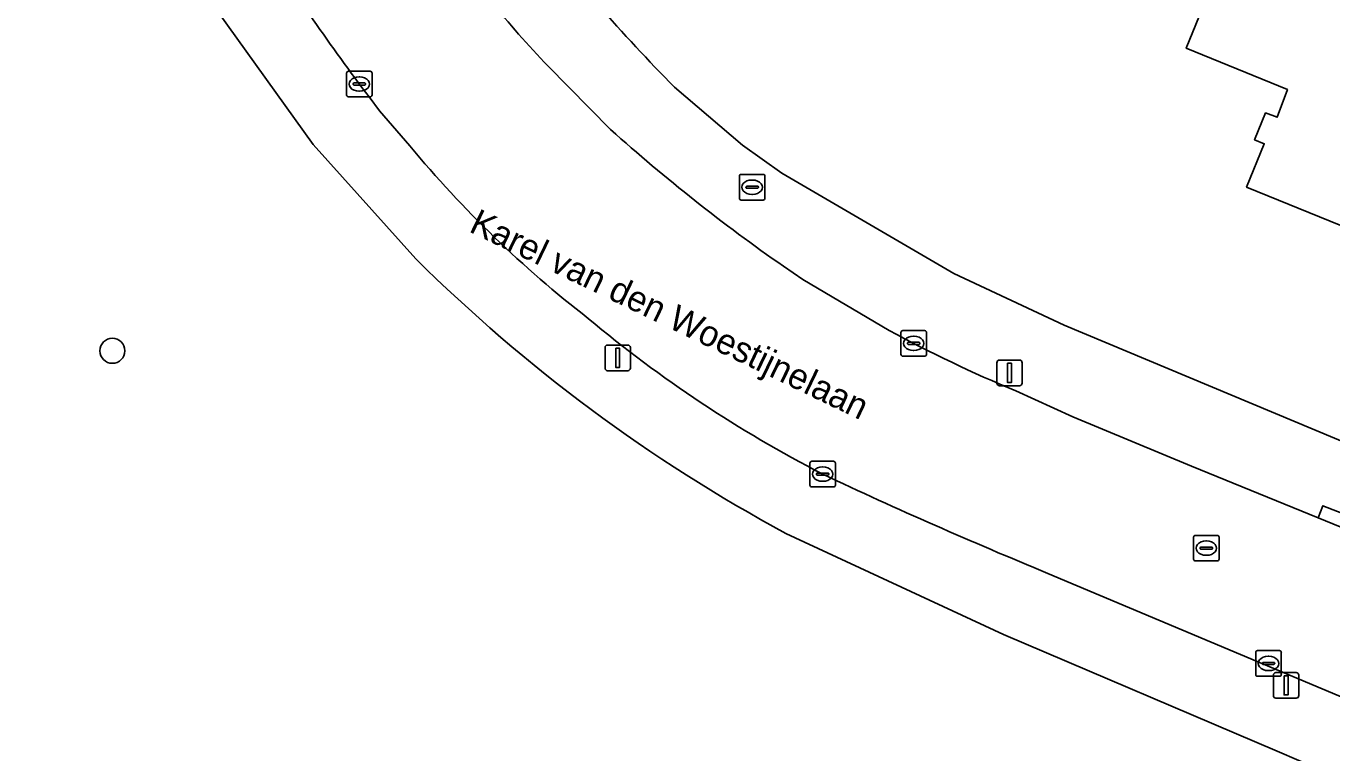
# Model space of a CAD drawing. Extents: x 161139 to 161601, y 381708 to 382245.
# Drawn here: x 161257.4 to 161308.4, y 381871.1 to 381899.5 of the extents above; entities that cross this region are included whole.
import ezdxf

# ---------------------------------------------------------------- set-up
doc = ezdxf.new("R2010")
doc.units = 0
for name, color, linetype in [('IMGEO_Boom', 7, 'Continuous'), ('IMGEO_Brandkraan', 7, 'Continuous'), ('IMGEO_Erf', 7, 'Continuous'), ('IMGEO_Groenvoorziening', 7, 'Continuous'), ('IMGEO_Kolk', 7, 'Continuous'), ('IMGEO_Lichtmast', 7, 'Continuous'), ('IMGEO_Openbare_ruimte_label', 7, 'Continuous'), ('IMGEO_Pand', 7, 'Continuous'), ('IMGEO_Rijbaan_lokaal_open', 7, 'Continuous'), ('IMGEO_Rioolput', 7, 'Continuous'), ('IMGEO_Voetpad_open', 7, 'Continuous')]:
    doc.layers.add(name, color=color, linetype=linetype)

msp = doc.modelspace()

# ---------------------------------------------------------------- linework, layer by layer
at = {"layer": 'IMGEO_Boom'}
msp.add_circle((161260.788, 381886.858), 0.489, dxfattribs=at)
at = {"layer": 'IMGEO_Brandkraan'}
for p, q in [((161285.289, 381892.824), (161285.289, 381893.676)), ((161285.364, 381893.75), (161286.216, 381893.75)), ((161285.777, 381893.53), (161285.802, 381893.53)), ((161286.29, 381893.676), (161286.29, 381892.824)), ((161285.548, 381893.244), (161285.548, 381893.256)), ((161285.986, 381893.207), (161285.588, 381893.207)), ((161285.591, 381893.293), (161285.989, 381893.293)), ((161286.032, 381893.256), (161286.032, 381893.244)), ((161286.216, 381892.75), (161285.364, 381892.75)), ((161285.8, 381892.97), (161285.775, 381892.97))]:
    msp.add_line(p, q, dxfattribs=at)
for points in [[(161285.289, 381892.824), (161285.289, 381893.676)], [(161285.364, 381893.75), (161286.216, 381893.75)], [(161286.29, 381893.676), (161286.29, 381892.824)], [(161286.216, 381892.75), (161285.364, 381892.75)]]:
    msp.add_lwpolyline(points, dxfattribs=at)
for centre, radius, start, end in [((161285.366, 381893.674), 0.0765, 91.552, 178.448), ((161285.366, 381893.674), 0.0765, 91.552, 178.448), ((161286.214, 381893.674), 0.0765, 1.552, 88.448), ((161286.214, 381893.674), 0.0765, 1.552, 88.448), ((161285.588, 381893.253), 0.0403, 85.8775, 175.7526), ((161285.585, 381893.243), 0.0366, 178.938, 274.7102), ((161285.989, 381893.25), 0.043, 264.8664, 352.4533), ((161285.993, 381893.255), 0.0386, 1.7309, 96.639), ((161285.366, 381892.826), 0.0765, 181.552, 268.448), ((161285.366, 381892.826), 0.0765, 181.552, 268.448), ((161286.214, 381892.826), 0.0765, 271.552, 358.448), ((161286.214, 381892.826), 0.0765, 271.552, 358.448)]:
    msp.add_arc(centre, radius, start, end, dxfattribs=at)
for centre, major_axis, ratio, start_param, end_param in [((161285.776, 381893.25), (-0.387, 0.002), 0.722429, 4.712389, 7.853982), ((161285.801, 381893.25), (-0.39, 0.002), 0.717154, 1.570796, 4.712389)]:
    msp.add_ellipse(centre, major_axis=major_axis, ratio=ratio, start_param=start_param, end_param=end_param, dxfattribs=at)
at = {"layer": 'IMGEO_Erf'}
msp.add_lwpolyline([(161316.193, 381910.265), (161323.278, 381907.381), (161321.194, 381902.259), (161317.489, 381903.766), (161313.947, 381895.06), (161312.062, 381890.428), (161305.111, 381893.257), (161305.8, 381894.95), (161305.424, 381895.103), (161305.852, 381896.154), (161306.302, 381895.986), (161306.706, 381897.067), (161302.753, 381898.676), (161306.145, 381907.012), (161310.258, 381905.339), (161309.82, 381904.264), (161313.34, 381902.832), (161314.245, 381905.055), (161314.097, 381905.115)], close=True, dxfattribs=at)
msp.add_lwpolyline([(161282.757, 381897.162), (161285.416, 381894.897), (161286.952, 381893.797), (161293.664, 381889.876), (161297.982, 381887.859), (161317.522, 381879.697)], dxfattribs=at)
msp.add_arc((161325.918, 381940.222), 60.967, 216.71398, 224.93243, dxfattribs=at)
at = {"layer": 'IMGEO_Groenvoorziening'}
for points in [[(161272.651, 381890.451), (161268.63, 381894.919), (161264.924, 381900.093), (161261.387, 381906.491)], [(161307.156, 381870.851), (161306.308, 381871.219), (161295.616, 381875.775), (161287.109, 381879.723)]]:
    msp.add_lwpolyline(points, dxfattribs=at)
msp.add_arc((161316.981, 381935.088), 62.91, 225.19754, 241.65079, dxfattribs=at)
at = {"layer": 'IMGEO_Kolk'}
for p, q in [((161269.938, 381896.854), (161269.938, 381897.706)), ((161270.013, 381897.78), (161270.865, 381897.78)), ((161270.939, 381897.706), (161270.939, 381896.854)), ((161270.197, 381897.274), (161270.197, 381897.286)), ((161270.635, 381897.237), (161270.237, 381897.237)), ((161270.24, 381897.323), (161270.638, 381897.323)), ((161270.426, 381897.56), (161270.451, 381897.56)), ((161270.681, 381897.286), (161270.681, 381897.274)), ((161270.865, 381896.78), (161270.013, 381896.78)), ((161270.449, 381897), (161270.424, 381897)), ((161291.601, 381886.722), (161291.601, 381887.574)), ((161291.676, 381887.648), (161292.528, 381887.648)), ((161292.089, 381887.428), (161292.114, 381887.428)), ((161292.602, 381887.574), (161292.602, 381886.722)), ((161291.86, 381887.142), (161291.86, 381887.154)), ((161292.298, 381887.105), (161291.9, 381887.105)), ((161291.903, 381887.191), (161292.301, 381887.191)), ((161292.344, 381887.154), (161292.344, 381887.142)), ((161292.528, 381886.648), (161291.676, 381886.648)), ((161292.112, 381886.868), (161292.087, 381886.868)), ((161288.043, 381881.614), (161288.043, 381882.466)), ((161288.118, 381882.54), (161288.97, 381882.54)), ((161288.531, 381882.32), (161288.556, 381882.32)), ((161289.044, 381882.466), (161289.044, 381881.614)), ((161288.302, 381882.034), (161288.302, 381882.046)), ((161288.74, 381881.997), (161288.342, 381881.997)), ((161288.345, 381882.083), (161288.743, 381882.083)), ((161288.786, 381882.046), (161288.786, 381882.034)), ((161288.97, 381881.54), (161288.118, 381881.54)), ((161288.554, 381881.76), (161288.529, 381881.76)), ((161305.541, 381875.143), (161306.393, 381875.143)), ((161305.466, 381874.217), (161305.466, 381875.069)), ((161305.725, 381874.637), (161305.725, 381874.649)), ((161305.768, 381874.686), (161306.166, 381874.686)), ((161305.954, 381874.923), (161305.979, 381874.923)), ((161306.209, 381874.649), (161306.209, 381874.637)), ((161306.467, 381875.069), (161306.467, 381874.217)), ((161306.393, 381874.143), (161305.541, 381874.143)), ((161306.163, 381874.6), (161305.765, 381874.6)), ((161305.977, 381874.363), (161305.952, 381874.363))]:
    msp.add_line(p, q, dxfattribs=at)
for points in [[(161269.938, 381896.854), (161269.938, 381897.706)], [(161270.013, 381897.78), (161270.865, 381897.78)], [(161270.939, 381897.706), (161270.939, 381896.854)], [(161270.865, 381896.78), (161270.013, 381896.78)], [(161291.601, 381886.722), (161291.601, 381887.574)], [(161291.676, 381887.648), (161292.528, 381887.648)], [(161292.602, 381887.574), (161292.602, 381886.722)], [(161292.528, 381886.648), (161291.676, 381886.648)], [(161288.043, 381881.614), (161288.043, 381882.466)], [(161288.118, 381882.54), (161288.97, 381882.54)], [(161289.044, 381882.466), (161289.044, 381881.614)], [(161288.97, 381881.54), (161288.118, 381881.54)], [(161305.541, 381875.143), (161306.393, 381875.143)], [(161305.466, 381874.217), (161305.466, 381875.069)], [(161306.467, 381875.069), (161306.467, 381874.217)], [(161306.393, 381874.143), (161305.541, 381874.143)]]:
    msp.add_lwpolyline(points, dxfattribs=at)
for centre, radius, start, end in [((161270.015, 381897.704), 0.0765, 91.552, 178.448), ((161270.015, 381897.704), 0.0765, 91.552, 178.448), ((161270.863, 381897.704), 0.0765, 1.552, 88.448), ((161270.863, 381897.704), 0.0765, 1.552, 88.448), ((161270.237, 381897.283), 0.0403, 85.8775, 175.7526), ((161270.234, 381897.273), 0.0366, 178.938, 274.7102), ((161270.638, 381897.28), 0.043, 264.8664, 352.4533), ((161270.642, 381897.285), 0.0386, 1.7309, 96.639), ((161270.015, 381896.856), 0.0765, 181.552, 268.448), ((161270.015, 381896.856), 0.0765, 181.552, 268.448), ((161270.863, 381896.856), 0.0765, 271.552, 358.448), ((161270.863, 381896.856), 0.0765, 271.552, 358.448), ((161291.678, 381887.572), 0.0765, 91.552, 178.448), ((161291.678, 381887.572), 0.0765, 91.552, 178.448), ((161292.526, 381887.572), 0.0765, 1.552, 88.448), ((161292.526, 381887.572), 0.0765, 1.552, 88.448), ((161291.9, 381887.151), 0.0403, 85.8775, 175.7526), ((161291.897, 381887.141), 0.0366, 178.938, 274.7102), ((161292.301, 381887.148), 0.043, 264.8664, 352.4533), ((161292.305, 381887.153), 0.0386, 1.7309, 96.639), ((161291.678, 381886.724), 0.0765, 181.552, 268.448), ((161291.678, 381886.724), 0.0765, 181.552, 268.448), ((161292.526, 381886.724), 0.0765, 271.552, 358.448), ((161292.526, 381886.724), 0.0765, 271.552, 358.448), ((161288.12, 381882.464), 0.0765, 91.552, 178.448), ((161288.12, 381882.464), 0.0765, 91.552, 178.448), ((161288.968, 381882.464), 0.0765, 1.552, 88.448), ((161288.968, 381882.464), 0.0765, 1.552, 88.448), ((161288.342, 381882.043), 0.0403, 85.8775, 175.7526), ((161288.339, 381882.033), 0.0366, 178.938, 274.7102), ((161288.743, 381882.04), 0.043, 264.8664, 352.4533), ((161288.747, 381882.045), 0.0386, 1.7309, 96.639), ((161288.12, 381881.616), 0.0765, 181.552, 268.448), ((161288.12, 381881.616), 0.0765, 181.552, 268.448), ((161288.968, 381881.616), 0.0765, 271.552, 358.448), ((161288.968, 381881.616), 0.0765, 271.552, 358.448), ((161305.543, 381875.067), 0.0765, 91.552, 178.448), ((161305.543, 381875.067), 0.0765, 91.552, 178.448), ((161306.391, 381875.067), 0.0765, 1.552, 88.448), ((161306.391, 381875.067), 0.0765, 1.552, 88.448), ((161305.765, 381874.646), 0.0403, 85.8775, 175.7526), ((161305.762, 381874.636), 0.0366, 178.938, 274.7102), ((161306.166, 381874.643), 0.043, 264.8664, 352.4533), ((161306.17, 381874.648), 0.0386, 1.7309, 96.639), ((161305.543, 381874.219), 0.0765, 181.552, 268.448), ((161305.543, 381874.219), 0.0765, 181.552, 268.448), ((161306.391, 381874.219), 0.0765, 271.552, 358.448), ((161306.391, 381874.219), 0.0765, 271.552, 358.448)]:
    msp.add_arc(centre, radius, start, end, dxfattribs=at)
for centre, major_axis, ratio, start_param, end_param in [((161270.425, 381897.28), (-0.387, 0.002), 0.722429, 4.712389, 7.853982), ((161270.45, 381897.28), (-0.39, 0.002), 0.717154, 1.570796, 4.712389), ((161292.088, 381887.148), (-0.387, 0.002), 0.722429, 4.712389, 7.853982), ((161292.113, 381887.148), (-0.39, 0.002), 0.717154, 1.570796, 4.712389), ((161288.53, 381882.04), (-0.387, 0.002), 0.722429, 4.712389, 7.853982), ((161288.555, 381882.04), (-0.39, 0.002), 0.717154, 1.570796, 4.712389), ((161305.953, 381874.643), (-0.387, 0.002), 0.722429, 4.712389, 7.853982), ((161305.978, 381874.643), (-0.39, 0.002), 0.717154, 1.570796, 4.712389)]:
    msp.add_ellipse(centre, major_axis=major_axis, ratio=ratio, start_param=start_param, end_param=end_param, dxfattribs=at)
at = {"layer": 'IMGEO_Lichtmast'}
for p, q in [((161280.041, 381886.182), (161280.041, 381886.982)), ((161280.041, 381886.982), (161280.041, 381886.182)), ((161280.141, 381887.082), (161280.931, 381887.082)), ((161280.931, 381887.082), (161280.141, 381887.082)), ((161281.031, 381886.982), (161281.031, 381886.182)), ((161281.031, 381886.182), (161281.031, 381886.982)), ((161295.349, 381885.594), (161295.349, 381886.394)), ((161295.349, 381886.394), (161295.349, 381885.594)), ((161295.449, 381886.494), (161296.239, 381886.494)), ((161296.239, 381886.494), (161295.449, 381886.494)), ((161296.339, 381886.394), (161296.339, 381885.594)), ((161296.339, 381885.594), (161296.339, 381886.394)), ((161280.931, 381886.082), (161280.141, 381886.082)), ((161280.141, 381886.082), (161280.931, 381886.082)), ((161296.239, 381885.494), (161295.449, 381885.494)), ((161295.449, 381885.494), (161296.239, 381885.494)), ((161306.158, 381873.386), (161306.158, 381874.186)), ((161306.158, 381874.186), (161306.158, 381873.386)), ((161306.258, 381874.286), (161307.048, 381874.286)), ((161307.048, 381874.286), (161306.258, 381874.286)), ((161307.148, 381874.186), (161307.148, 381873.386)), ((161307.148, 381873.386), (161307.148, 381874.186)), ((161307.048, 381873.286), (161306.258, 381873.286)), ((161306.258, 381873.286), (161307.048, 381873.286))]:
    msp.add_line(p, q, dxfattribs=at)
for points in [[(161280.461, 381886.957), (161280.611, 381886.957), (161280.611, 381886.207), (161280.461, 381886.207), (161280.461, 381886.957)], [(161295.769, 381886.369), (161295.919, 381886.369), (161295.919, 381885.619), (161295.769, 381885.619), (161295.769, 381886.369)], [(161306.578, 381874.161), (161306.728, 381874.161), (161306.728, 381873.411), (161306.578, 381873.411), (161306.578, 381874.161)]]:
    msp.add_lwpolyline(points, dxfattribs=at)
for centre, start, end in [((161280.141, 381886.982), 90, 180), ((161280.141, 381886.982), 90, 180), ((161280.931, 381886.982), 0, 90), ((161280.931, 381886.982), 360, 90), ((161295.449, 381886.394), 90, 180), ((161295.449, 381886.394), 90, 180), ((161296.239, 381886.394), 0, 90), ((161296.239, 381886.394), 360, 90), ((161280.141, 381886.182), 180, 270), ((161280.141, 381886.182), 180, 270), ((161280.931, 381886.182), 270, 0), ((161280.931, 381886.182), 270, 0), ((161295.449, 381885.594), 180, 270), ((161295.449, 381885.594), 180, 270), ((161296.239, 381885.594), 270, 0), ((161296.239, 381885.594), 270, 0), ((161306.258, 381874.186), 90, 180), ((161306.258, 381874.186), 90, 180), ((161307.048, 381874.186), 0, 90), ((161307.048, 381874.186), 360, 90), ((161306.258, 381873.386), 180, 270), ((161306.258, 381873.386), 180, 270), ((161307.048, 381873.386), 270, 0), ((161307.048, 381873.386), 270, 0)]:
    msp.add_arc(centre, 0.1, start, end, dxfattribs=at)
at = {"layer": 'IMGEO_Pand'}
msp.add_lwpolyline([(161312.062, 381890.428), (161313.947, 381895.06), (161317.489, 381903.766), (161321.194, 381902.259), (161323.278, 381907.381), (161316.193, 381910.265), (161314.097, 381905.115), (161314.245, 381905.055), (161313.34, 381902.832), (161309.82, 381904.264), (161310.258, 381905.339), (161306.145, 381907.012), (161302.753, 381898.676), (161306.706, 381897.067), (161306.302, 381895.986), (161305.852, 381896.154), (161305.424, 381895.103), (161305.8, 381894.95), (161305.111, 381893.257)], close=True, dxfattribs=at)
at = {"layer": 'IMGEO_Rijbaan_lokaal_open'}
for points in [[(161280.259, 381895.503), (161277.808, 381897.987)], [(161270.816, 381896.775), (161271.228, 381896.235), (161272.414, 381894.865)], [(161291.143, 381887.655), (161287.77, 381889.643), (161287.39, 381889.901), (161287.011, 381890.162)], [(161321.429, 381875.549), (161318.426, 381876.273), (161316.431, 381876.868), (161312.405, 381878.498), (161307.913, 381880.338), (161302.959, 381882.345), (161298.323, 381884.279), (161296.095, 381885.289)], [(161297.345, 381878.162), (161313.303, 381871.448)]]:
    msp.add_lwpolyline(points, dxfattribs=at)
for centre, radius, start, end in [((161357.146, 381961.507), 107.903, 212.90543, 216.8632), ((161305.516, 381924.595), 38.415, 218.7964, 223.8402), ((161326.411, 381946.909), 69.084, 228.08278, 235.22747), ((161306.253, 381922.87), 43.924, 219.6115, 232.2855), ((161311.453, 381926.489), 50.005, 230.1076, 242.7376), ((161316.865, 381935.126), 53.992, 241.5489, 247.3754), ((161368.588, 382051.732), 187.622, 244.748, 247.68406)]:
    msp.add_arc(centre, radius, start, end, dxfattribs=at)
at = {"layer": 'IMGEO_Rioolput'}
for p, q in [((161303.035, 381878.722), (161303.035, 381879.574)), ((161303.11, 381879.648), (161303.962, 381879.648)), ((161303.523, 381879.428), (161303.548, 381879.428)), ((161304.036, 381879.574), (161304.036, 381878.722)), ((161303.294, 381879.142), (161303.294, 381879.154)), ((161303.732, 381879.105), (161303.334, 381879.105)), ((161303.337, 381879.191), (161303.735, 381879.191)), ((161303.546, 381878.868), (161303.521, 381878.868)), ((161303.778, 381879.154), (161303.778, 381879.142)), ((161303.962, 381878.648), (161303.11, 381878.648))]:
    msp.add_line(p, q, dxfattribs=at)
for points in [[(161303.035, 381878.722), (161303.035, 381879.574)], [(161303.11, 381879.648), (161303.962, 381879.648)], [(161304.036, 381879.574), (161304.036, 381878.722)], [(161303.962, 381878.648), (161303.11, 381878.648)]]:
    msp.add_lwpolyline(points, dxfattribs=at)
for centre, radius, start, end in [((161303.112, 381879.572), 0.0765, 91.552, 178.448), ((161303.112, 381879.572), 0.0765, 91.552, 178.448), ((161303.96, 381879.572), 0.0765, 1.552, 88.448), ((161303.96, 381879.572), 0.0765, 1.552, 88.448), ((161303.112, 381878.724), 0.0765, 181.552, 268.448), ((161303.112, 381878.724), 0.0765, 181.552, 268.448), ((161303.334, 381879.151), 0.0403, 85.8775, 175.7526), ((161303.331, 381879.141), 0.0366, 178.938, 274.7102), ((161303.735, 381879.148), 0.043, 264.8664, 352.4533), ((161303.739, 381879.153), 0.0386, 1.7309, 96.639), ((161303.96, 381878.724), 0.0765, 271.552, 358.448), ((161303.96, 381878.724), 0.0765, 271.552, 358.448)]:
    msp.add_arc(centre, radius, start, end, dxfattribs=at)
for centre, major_axis, ratio, start_param, end_param in [((161303.522, 381879.148), (-0.387, 0.002), 0.722429, 4.712389, 7.853982), ((161303.547, 381879.148), (-0.39, 0.002), 0.717154, 1.570796, 4.712389)]:
    msp.add_ellipse(centre, major_axis=major_axis, ratio=ratio, start_param=start_param, end_param=end_param, dxfattribs=at)
at = {"layer": 'IMGEO_Voetpad_open'}
for points in [[(161257.417, 381917.229), (161259.539, 381911.147), (161261.387, 381906.491), (161264.924, 381900.093), (161268.63, 381894.919), (161272.651, 381890.451)], [(161277.808, 381897.987), (161280.259, 381895.503)], [(161317.522, 381879.697), (161297.982, 381887.859), (161293.664, 381889.876), (161286.952, 381893.797), (161285.416, 381894.897), (161282.757, 381897.162)], [(161272.414, 381894.865), (161271.228, 381896.235), (161270.816, 381896.775)], [(161287.011, 381890.162), (161287.39, 381889.901), (161287.77, 381889.643), (161291.143, 381887.655)], [(161296.095, 381885.289), (161298.323, 381884.279), (161302.959, 381882.345), (161307.913, 381880.338), (161308.089, 381880.805), (161318.602, 381876.74), (161318.426, 381876.273), (161321.429, 381875.549)], [(161287.109, 381879.723), (161295.616, 381875.775), (161306.308, 381871.219), (161307.156, 381870.851), (161311.091, 381869.145), (161314.407, 381867.708)], [(161313.303, 381871.448), (161297.345, 381878.162)]]:
    msp.add_lwpolyline(points, dxfattribs=at)
msp.add_lwpolyline([(161318.426, 381876.273), (161318.602, 381876.74), (161308.089, 381880.805), (161307.913, 381880.338), (161312.405, 381878.498), (161316.431, 381876.868)], close=True, dxfattribs=at)
for centre, radius, start, end in [((161325.918, 381940.222), 60.967, 216.71398, 224.93243), ((161357.146, 381961.507), 107.903, 212.90543, 216.8632), ((161305.516, 381924.595), 38.415, 218.7964, 223.8402), ((161326.411, 381946.909), 69.084, 228.08278, 235.22747), ((161306.253, 381922.87), 43.924, 219.6115, 232.2855), ((161316.981, 381935.088), 62.91, 225.19754, 241.65079), ((161311.453, 381926.489), 50.005, 230.1076, 242.7376), ((161316.865, 381935.126), 53.992, 241.5489, 247.3754), ((161368.588, 382051.732), 187.622, 244.748, 247.68406)]:
    msp.add_arc(centre, radius, start, end, dxfattribs=at)

# ---------------------------------------------------------------- texts
at = {"layer": 'IMGEO_Openbare_ruimte_label'}
msp.add_text('Karel van den Woestijnelaan', height=1, rotation=334.2805, dxfattribs=at).set_placement((161274.682, 381891.533))

doc.saveas('drawing.dxf')
